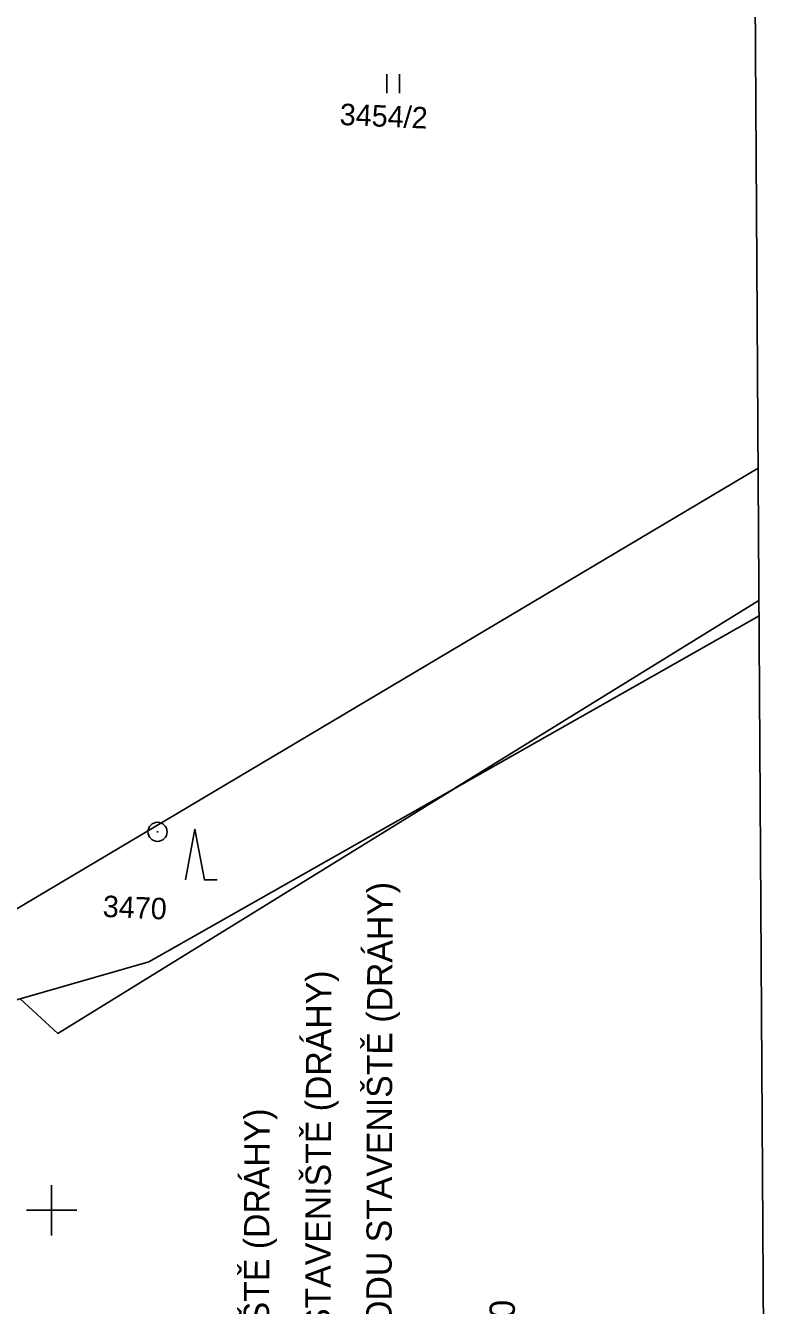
# Model space of a CAD drawing. Extents: x -735036 to -734743, y -1144813 to -1144181.
# Drawn here: x -734802.1 to -734743, y -1144707.5 to -1144606.2 of the extents above; entities that cross this region are included whole.
import ezdxf

# ---------------------------------------------------------------- set-up
doc = ezdxf.new("R2010")
doc.units = 0
for name, color, linetype in [('000_rozpiska', 7, 'Continuous'), ('BPEJ', 7, 'Continuous'), ('Katastr_Hranice parcel', 7, 'Continuous'), ('Katastr_Parcelní čísla', 7, 'Continuous'), ('Katastr_Značky kultur', 7, 'Continuous'), ('Vrstva 7', 7, 'Continuous'), ('čtvercová síť', 7, 'Continuous')]:
    doc.layers.add(name, color=color, linetype=linetype)

# ---------------------------------------------------------------- blocks, each defined once
blk = doc.blocks.new('C691')
at = {"layer": 'Vrstva 7'}
for p, q in [((0, 0.5), (0, -0.5)), ((-0.5, 0), (0.5, 0))]:
    blk.add_line(p, q, dxfattribs=at)

msp = doc.modelspace()

# ---------------------------------------------------------------- linework, layer by layer
at = {"layer": '000_rozpiska'}
msp.add_line((-734743.05, -1144810.64), (-734746.94, -1144180.65), dxfattribs=at)
at = {"layer": 'BPEJ'}
msp.add_lwpolyline([(-734802.5, -1144683.25), (-734799.5, -1144686), (-734768.16, -1144666.63), (-734768.09, -1144666.59), (-734744.03, -1144651.73)], dxfattribs=at)
at = {"layer": 'Defpoints'}
msp.add_line((-734743.05, -1144810.64), (-734745.64, -1144390.65), dxfattribs=at)
at = {"layer": 'Katastr_Hranice parcel'}
for points in [[(-734744.09, -1144641.26), (-734803.06, -1144676.31)], [(-734790.91, -1144679.53), (-734744.02, -1144652.95)], [(-734792.32, -1144680.32), (-734790.91, -1144679.53)], [(-734809.02, -1144685.13), (-734792.32, -1144680.32)]]:
    msp.add_lwpolyline(points, dxfattribs=at)
at = {"layer": 'Katastr_Značky kultur'}
for p, q in [((-734773.47, -1144610.06), (-734773.47, -1144611.56)), ((-734772.47, -1144611.56), (-734772.47, -1144610.06)), ((-734791.67, -1144670.04), (-734791.57, -1144670.04))]:
    msp.add_line(p, q, dxfattribs=at)
msp.add_lwpolyline([(-734789.41, -1144673.84), (-734788.66, -1144669.84), (-734787.91, -1144673.84), (-734786.91, -1144673.84)], dxfattribs=at)
msp.add_circle((-734791.62, -1144670.04), 0.756, dxfattribs=at)

# ---------------------------------------------------------------- block references
at = {"layer": 'čtvercová síť', "xscale": 4, "yscale": 4}
msp.add_blockref('C691', (-734800, -1144700), dxfattribs=at)

# ---------------------------------------------------------------- texts
for s, rotation, p in [('ČÍSLO LOMOVÉHO BODU DOČASNÉHO OBVODU STAVENIŠTĚ (DRÁHY)', 89.8464, (-734773.26, -1144766.29)), ('ČÍSLO LOMOVÉHO BODU UVNITŘ OBVODU STAVENIŠTĚ (DRÁHY)', 89.8464, (-734778.09, -1144766.02)), ('ČÍSLO LOMOVÉHO BODU OBVODU STAVENIŠTĚ (DRÁHY)', 89.8464, (-734782.95, -1144766.24)), ('KLAD LISTŮ KATASTRÁLNÍ MAPY 1:1000', 90.1523, (-734763.21, -1144758.66))]:
    msp.add_text(s, height=2, rotation=rotation).set_placement(p)
at = {"layer": 'Katastr_Parcelní čísla'}
for s, p in [('3454/2', (-734777.23, -1144614.08)), ('3470', (-734795.98, -1144676.77))]:
    msp.add_text(s, height=1.7, rotation=357.5604, dxfattribs=at).set_placement(p)

doc.saveas('drawing.dxf')
